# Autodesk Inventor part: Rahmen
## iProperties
Created: 2003-03
Part Number: Rahmen
Material: Aluminium
Document SubType Name: Modellieren
Designer: Administrator
Control State: 0
Master: False
Checked Out: False
Shininess: 20.0
Angle Display Precision: 2
Document Length Units: 11269
Document Angle Units: 11279
Document Time Units: 11290
Document Mass Units: 11283
Document Length Units Precision: 3
Document Angle Units Precision: 2
Density: 0.0
Volumn: 0.0
Area: 0.0
PropertySet Name: Model Information
Author: Administrator
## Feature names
1. Extrusion1
2. Extrusion2
3. Extrusion3
4. Rundung1 [Fillet]
5. Fase1 [Chamfer]
6. Bohrung1 [Hole]
